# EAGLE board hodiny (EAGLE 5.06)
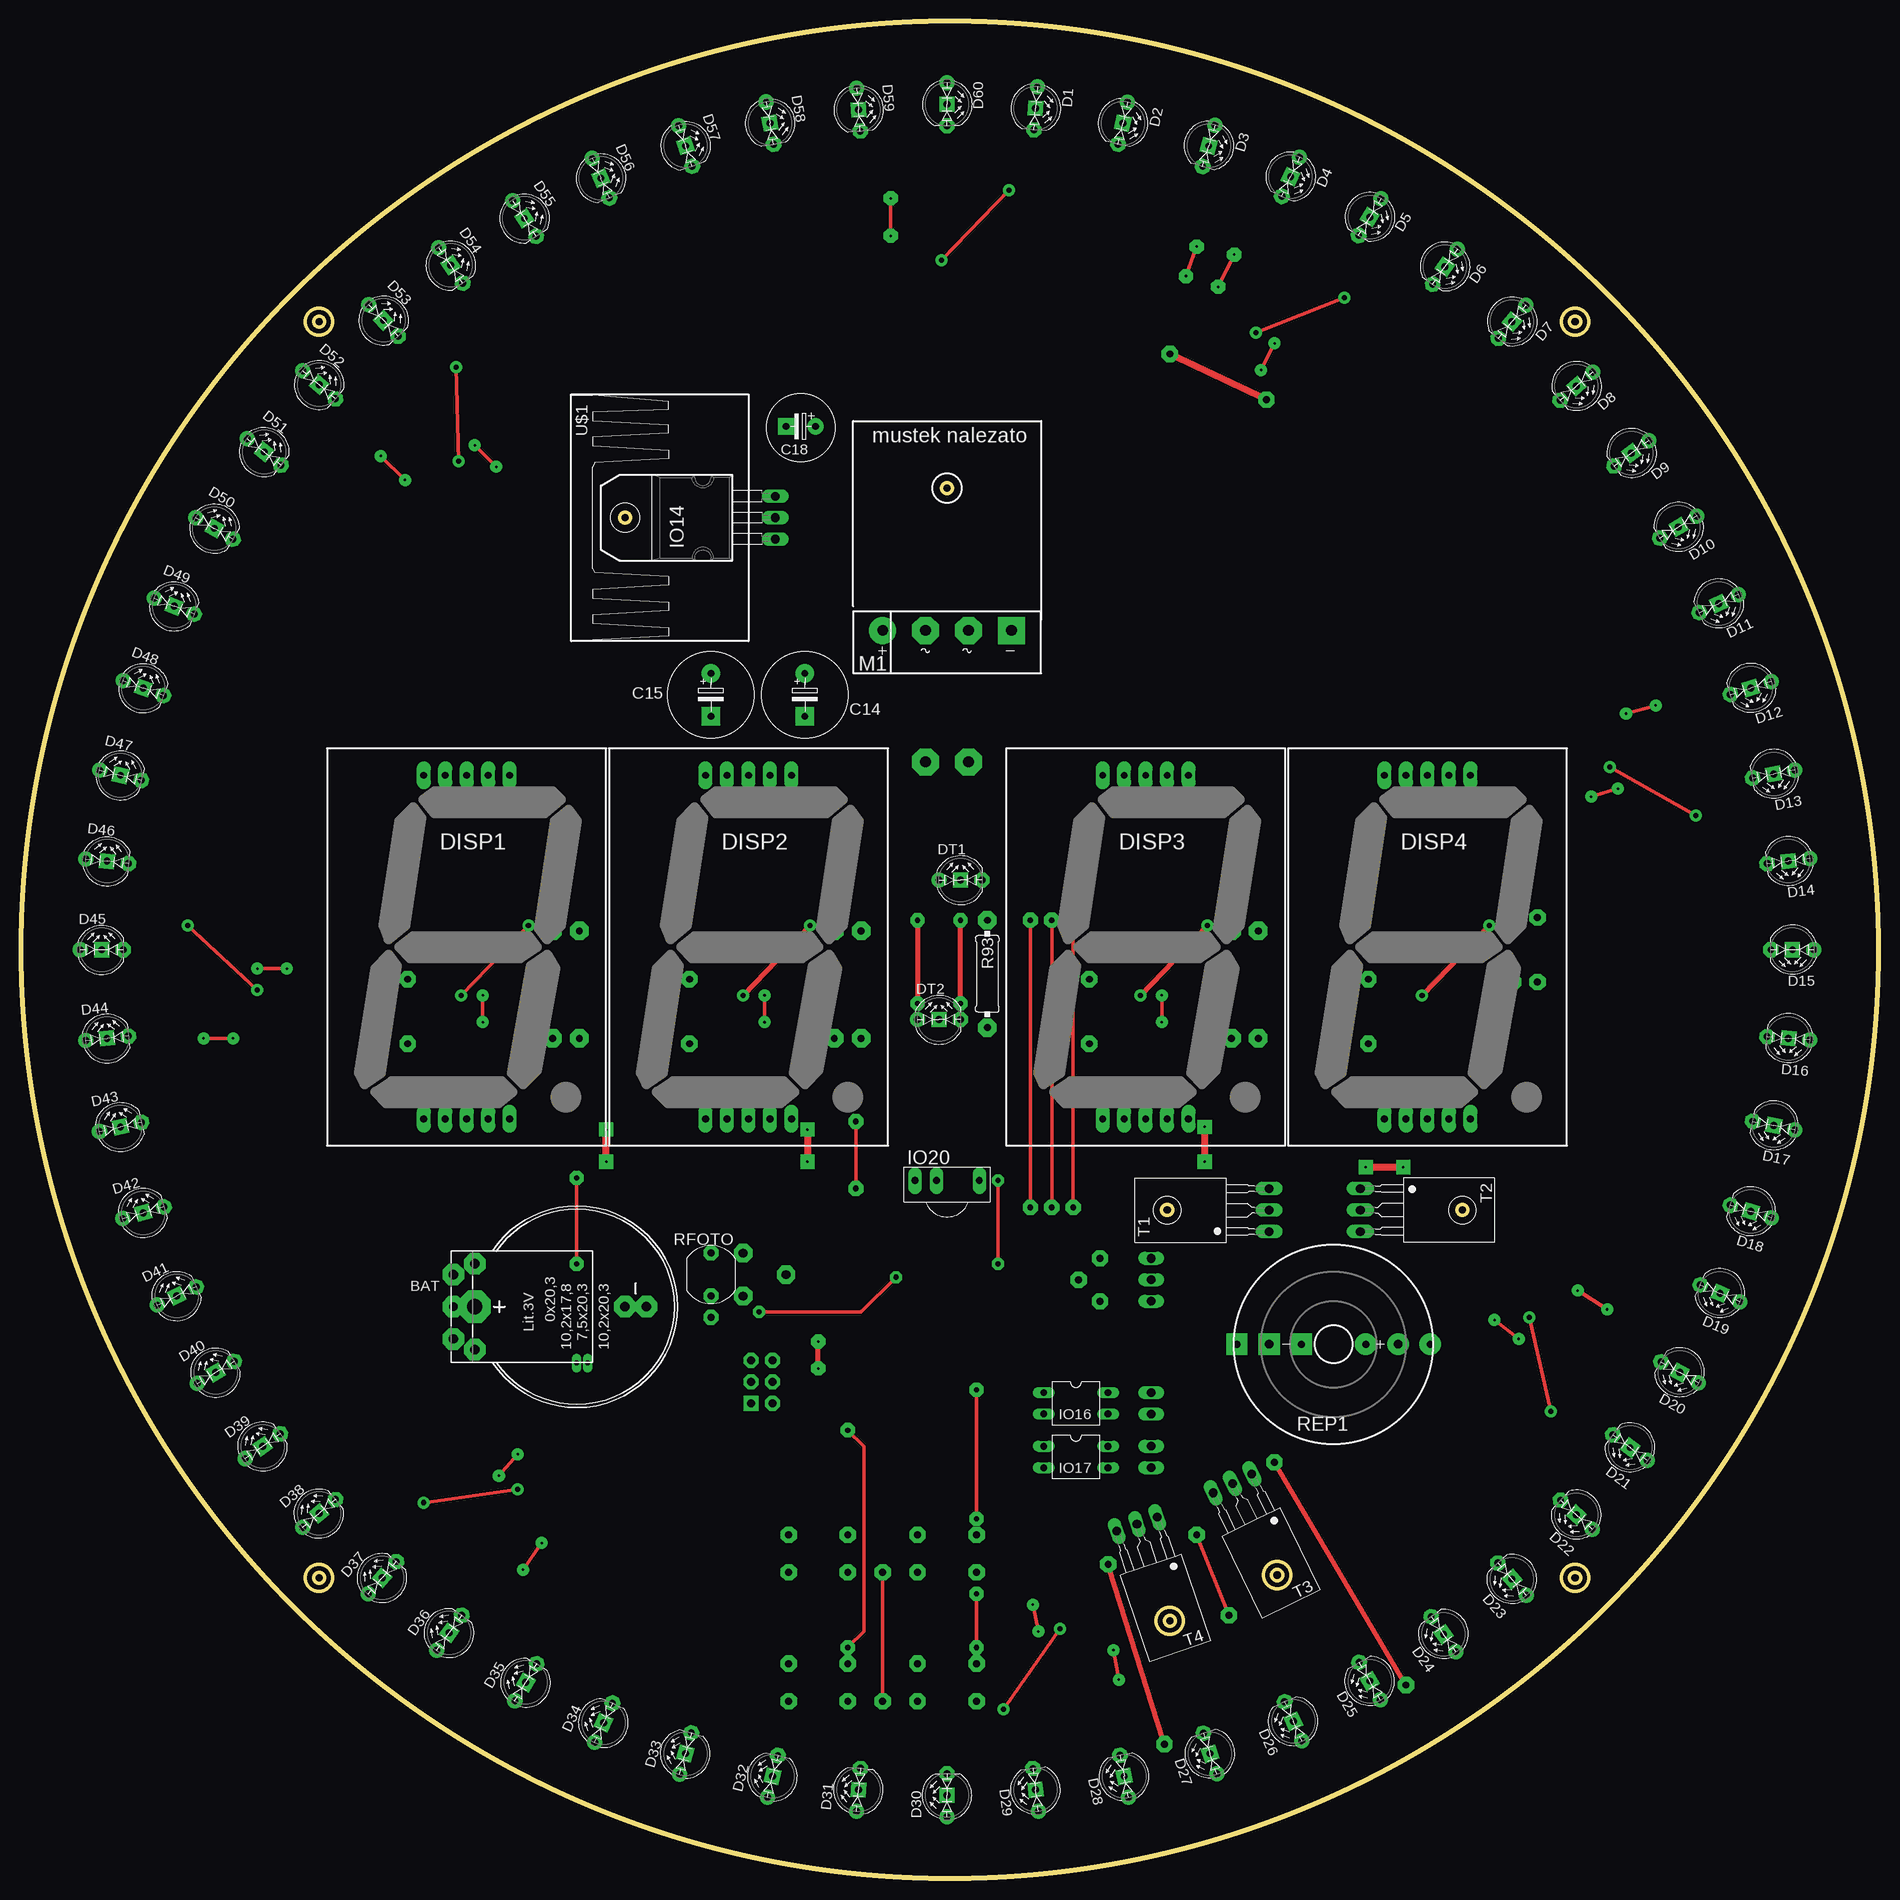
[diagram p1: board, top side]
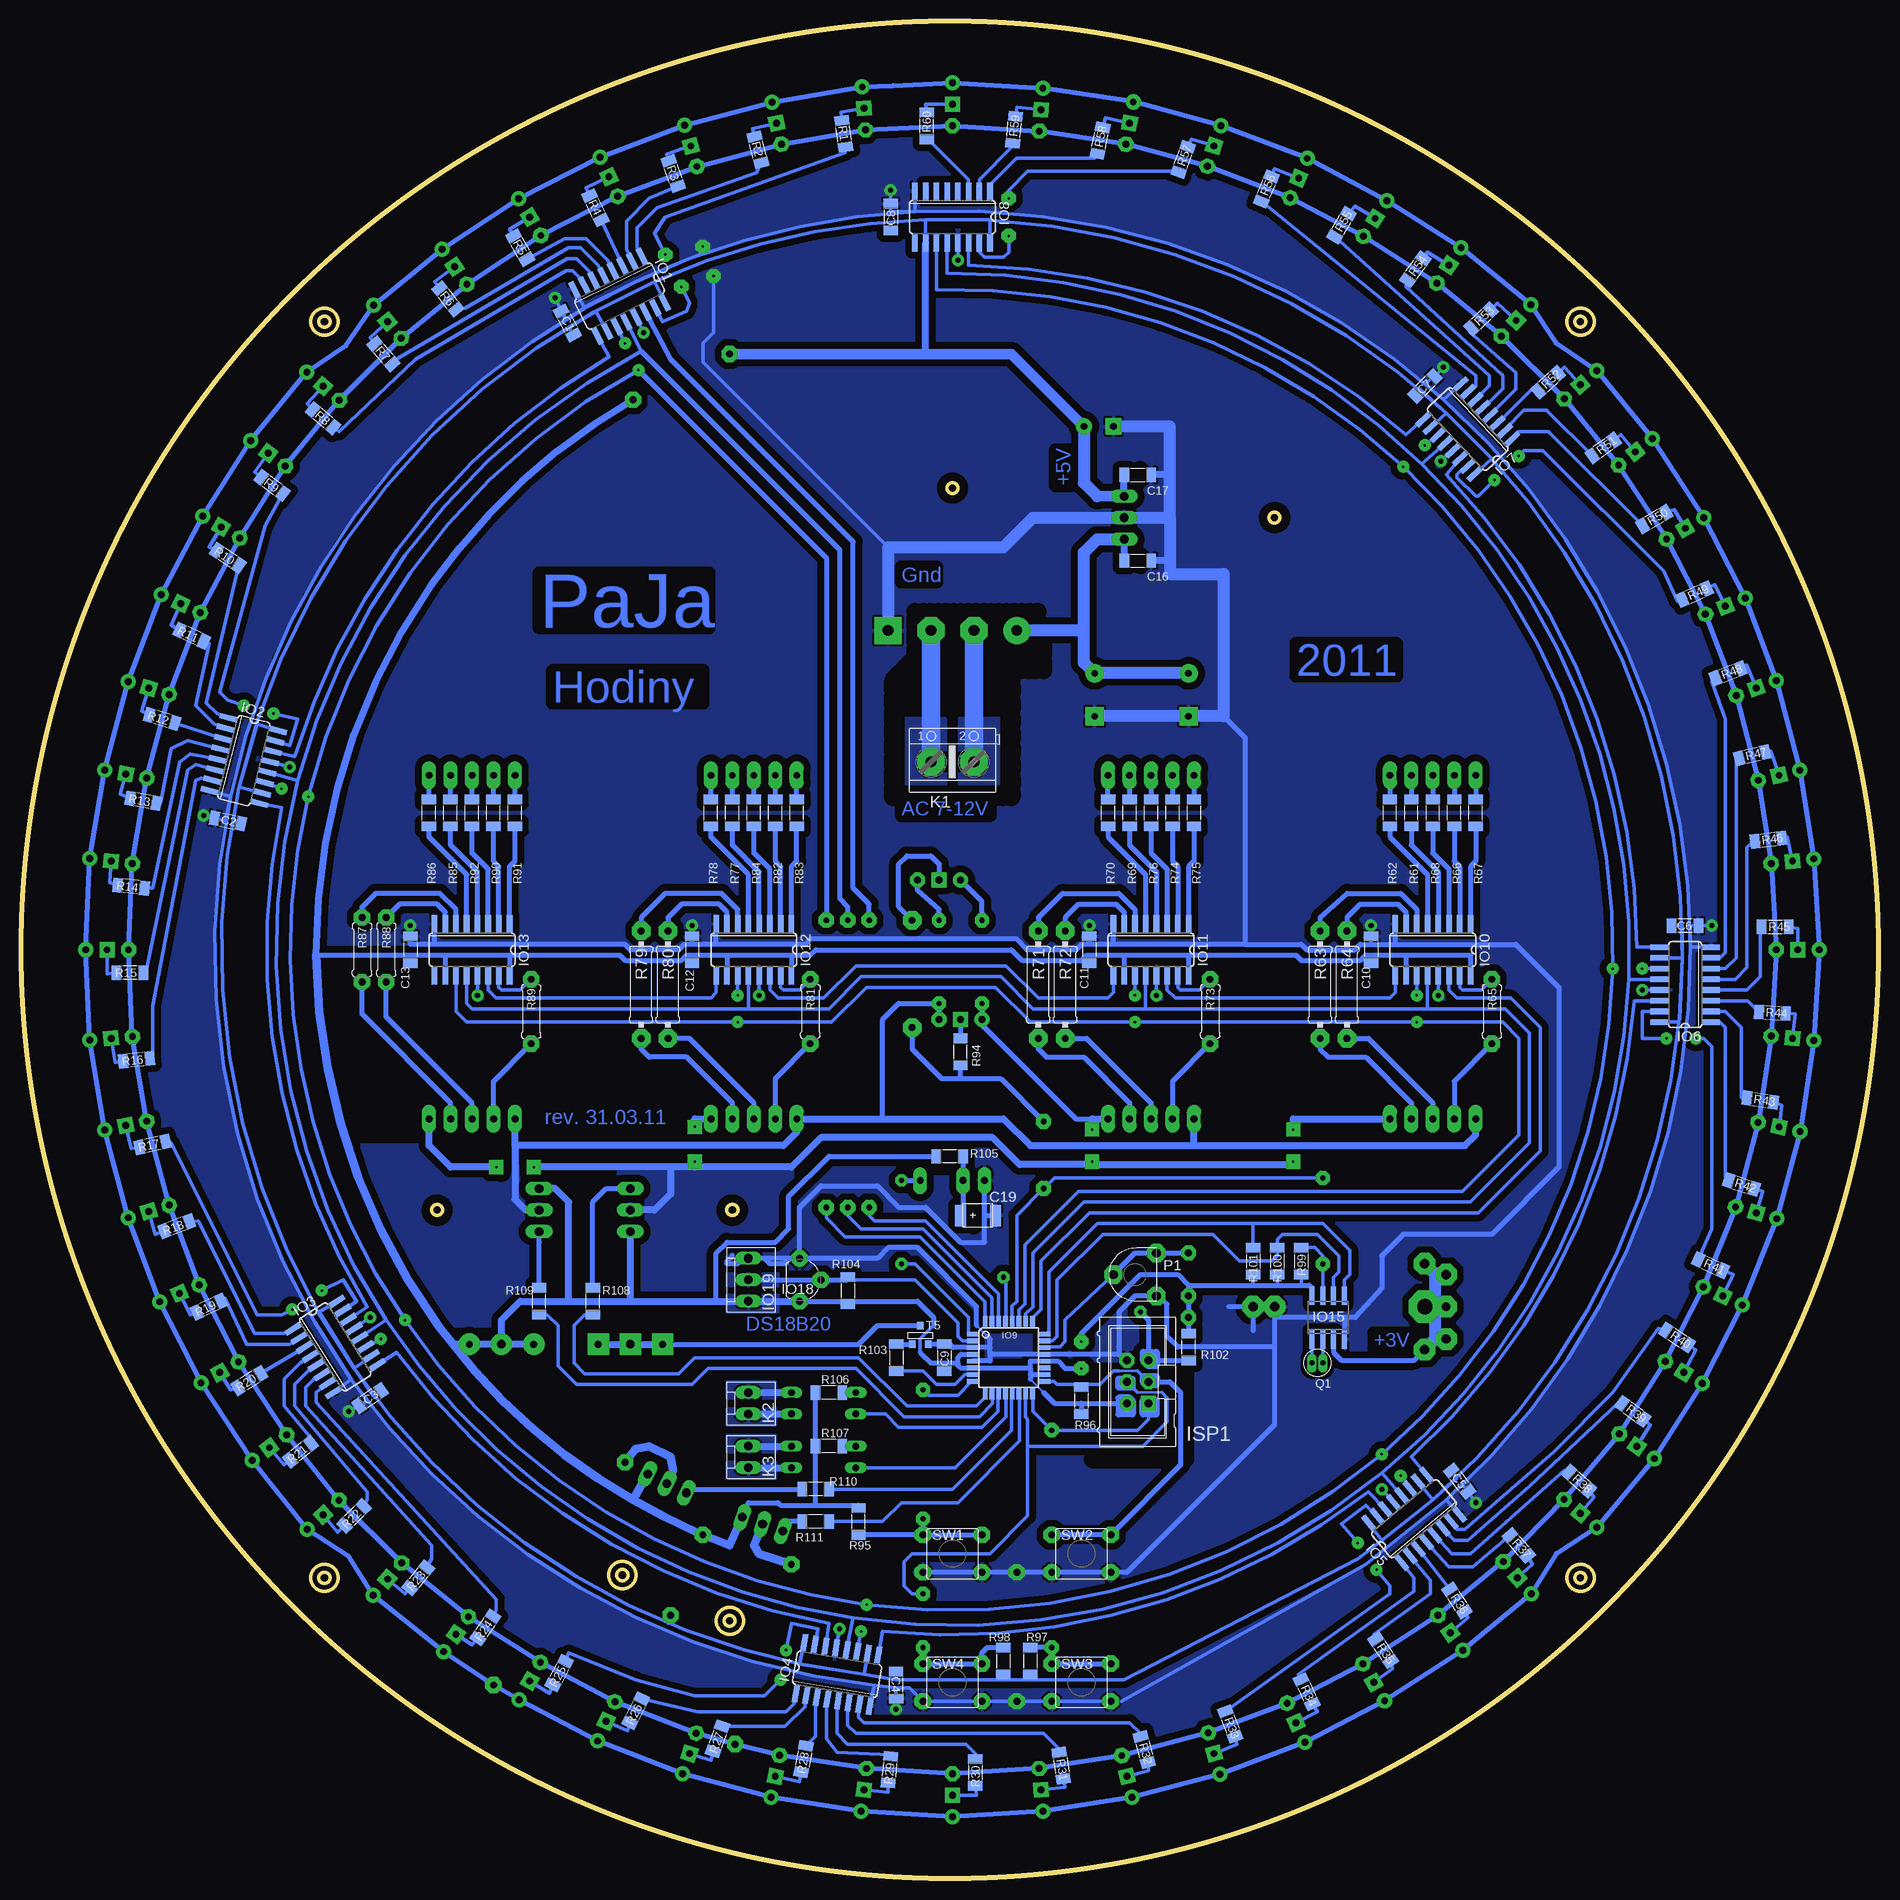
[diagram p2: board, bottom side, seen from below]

Size 219.71 x 219.71 mm. Coordinates in mm from the lower left corner, seen from the top.
Outline: circle at 109.86,109.86 radius 109.86
Outline: circle at 109.86,109.86 radius 109.86
Outline: circle at 109.86,109.86 radius 109.86
Outline: circle at 109.86,109.86 radius 109.86
Outline: circle at 109.54,164.47 radius 0.64
Outline: circle at 71.44,160.97 radius 0.64
Outline: circle at 35.24,184.15 radius 0.64
Outline: circle at 35.24,184.15 radius 1.59
Outline: circle at 183.83,184.15 radius 0.64
Outline: circle at 183.83,184.15 radius 1.59
Outline: circle at 183.83,35.56 radius 0.64
Outline: circle at 183.83,35.56 radius 1.59
Outline: circle at 35.24,35.56 radius 0.64
Outline: circle at 35.24,35.56 radius 1.59
Outline: circle at 148.59,35.88 radius 0.64
Outline: circle at 148.59,35.88 radius 1.59
Outline: circle at 135.89,30.48 radius 0.64
Outline: circle at 135.89,30.48 radius 1.59
Outline: circle at 135.57,79.06 radius 0.64
Outline: circle at 170.5,79.06 radius 0.64
Copper layers (1*16): Top 0.035mm / dielectric 1.5mm / Bottom 0.035mm
Design rules "default": minimum track width 10mil, minimum drill 24mil, track to track 8mil, track to pad 8mil, pad to pad 8mil, via to via 8mil, smd to smd 8mil, copper to edge 40mil, drill to drill 8mil, minimum pad ring 10mil, minimum via ring 8mil, stop-mask expansion 4mil, vias tented up to drill 0mil, thermal gap 10mil
bRestrict: area 81.9,62.2 to 86,67.3; 58 lines

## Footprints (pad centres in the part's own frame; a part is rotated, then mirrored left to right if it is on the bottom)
B2430UNI = drill 1.118 pad 2.54 octagon: + 3.81,14.605; +@1 -3.81,14.605; +@2 -5.08,12.065; +@3 5.08,12.065; - 0,-5.715; -@1 0,-8.255 | drill 1.803 pad 3.81 octagon: +@4 0,12.065
1206 = smd 1.143 x 1.702: 1 -1.587,0; 2 1.587,0
C_EL_5 = drill 0.813 pad 2.184 round: C+ -2.54,0 | drill 0.813 pad 2.184 square: C- 2.54,0
C_EL_3,5 = drill 0.813 pad 1.93 round: C+ 0,0 | drill 0.813 pad 1.93 square: C- 3.493,0
B = smd 1.27 x 2.54: + 2.223,0; - -1.905,0
LED_5-DUO = drill 0.813 pad 1.778 octagon: A1 2.54,0 | drill 0.813 pad 1.778 round: A2 -2.54,0 | drill 0.813 pad 1.778 square: K 0,0
HD-AB = drill 0.813 pad 1.676 long: 1 0,0; 2 2.54,0; 3 5.08,0; 4 7.62,0; 5 10.16,0; 6 10.16,40.64; 7 7.62,40.64; 8 5.08,40.64; 9 2.54,40.64; 10 0,40.64
SO16 = smd 0.66 x 2.032: 1 -4.445,-3.073; 2 -3.175,-3.073; 3 -1.905,-3.073; 4 -0.635,-3.073; 5 0.635,-3.073; 6 1.905,-3.073; 7 3.175,-3.073; 8 4.445,-3.073; 9 4.445,3.073; 10 3.175,3.073; 11 1.905,3.073; 12 0.635,3.073; 13 -0.635,3.073; 14 -1.905,3.073; 15 -3.175,3.073; 16 -4.445,3.073
TQFP32-08 = smd 1.27 x 0.559: 1 -4.293,2.8; 2 -4.293,2; 3 -4.293,1.2; 4 -4.293,0.4; 5 -4.293,-0.4; 6 -4.293,-1.2; 7 -4.293,-2; 8 -4.293,-2.8; 17 4.293,-2.8; 18 4.293,-2; 19 4.293,-1.2; 20 4.293,-0.4; 21 4.293,0.4; 22 4.293,1.2; 23 4.293,2; 24 4.293,2.8 | smd 0.559 x 1.27: 9 -2.8,-4.293; 10 -2,-4.293; 11 -1.2,-4.293; 12 -0.4,-4.293; 13 0.4,-4.293; 14 1.2,-4.293; 15 2,-4.293; 16 2.8,-4.293; 25 2.8,4.293; 26 2,4.293; 27 1.2,4.293; 28 0.4,4.293; 29 -0.4,4.293; 30 -1.2,4.293; 31 -2,4.293; 32 -2.8,4.293
TO-220 = drill 1.016 pad 1.6 long: 1 -2.54,0; 2 0,0; 3 2.54,0
SO08 = smd 0.6 x 2.2: 1 -1.905,-2.6; 2 -0.635,-2.6; 3 0.635,-2.6; 4 1.905,-2.6; 5 1.905,2.6; 6 0.635,2.6; 7 -0.635,2.6; 8 -1.905,2.6
DIL4 = drill 0.813 pad 1.27 long: 1 -1.27,-3.81; 2 1.27,-3.81; 3 1.27,3.81; 4 -1.27,3.81
TO-92 = drill 0.813 pad 1.93 octagon: 1 0,2.54; 2 2.54,0; 3 0,-2.54
PSH02-03P = drill 1.016 pad 1.422 long: 1 -2.54,0; 2 0,0; 3 2.54,0
SFH506 = drill 0.813 pad 1.6 long: 1 -3.81,0; 2 -1.27,0; 3 3.81,0
MLW06G = drill 0.914 pad 1.778 square: 1 -2.54,-1.27 | drill 0.914 pad 1.778 octagon: 2 -2.54,1.27; 3 0,-1.27; 4 0,1.27; 5 2.54,-1.27; 6 2.54,1.27
ARK500/2 = drill 1.27 pad 3.2 octagon: 1 -2.54,0; 2 2.54,0
PSH02-02P = drill 1.016 pad 1.422 long: 1 -1.27,0; 2 1.27,0
DM_KBU = drill 1.27 pad 3.2 round: + -7.62,2.857 | drill 1.27 pad 3.2 square: - 7.62,2.857 | drill 1.27 pad 3.2 octagon: AC1 -2.54,2.857; AC2 2.54,2.857
PT6V = drill 1.016 pad 2.184 octagon: 1 -2.54,-2.54; 2 0,2.54; 3 2.54,-2.54
Q_3X8 = drill 0.6 pad 0.813 long: 1 -0.635,0; 2 0.635,0
R-12,7 = drill 0.813 pad 2.184 octagon: 1 -6.35,0; 2 6.35,0
R-7,5 = drill 0.813 pad 1.93 octagon: 1 -3.81,0; 2 3.81,0
KPE212A = drill 1 pad 2.54 round: + -7.62,0 | drill 1 pad 2.54 square: - 7.62,0
R-FOTO = drill 0.813 pad 1.778 octagon: 1 -2.54,0; 2 2.54,0
P-B1720 = drill 0.813 pad 1.93 octagon: 1 -3.493,-2.223; 2 -3.493,2.223; 3 3.493,-2.223; 4 3.493,2.223
TO-126 = drill 1.016 pad 1.6 long: 1 -2.54,-12.065; 2 0,-12.065; 3 2.54,-12.065
SOT-23 = smd 0.787 x 0.889: 1 -0.953,-0.953; 2 0.953,-0.953; 3 0,1.27

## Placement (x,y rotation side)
BAT  CR2032  [B2430UNI]  65.72,67.63 90 top
C1  100n  [1206]  155.1,183.99 297.6 bottom
C2  100n  [1206]  195.26,125.09 348.6 bottom
C3  100n  [1206]  178.44,56.83 34.7 bottom
C4  100n  [1206]  116.21,22.86 90.1 bottom
C5  100n  [1206]  49.53,46.99 128 bottom
C6  100n  [1206]  22.86,112.71 180 bottom
C7  100n  [1206]  53.66,176.53 224.9 bottom
C8  100n  [1206]  116.84,196.53 270 bottom
C9  100n  [1206]  110.49,61.6 270 bottom
C10  100n  [1206]  60.01,109.86 270 bottom
C11  100n  [1206]  93.35,109.86 270 bottom
C12  100n  [1206]  140.34,109.86 270 bottom
C13  100n  [1206]  173.67,109.86 270 bottom
C14  470M/25V  [C_EL_5]  92.71,140.02 270 top
C15  470M/25V  [C_EL_5]  81.6,140.02 270 top
C16  100n  [1206]  87.63,155.89 0 bottom
C17  100n  [1206]  87.63,166.05 0 bottom
C18  220M/25V  [C_EL_3,5]  93.98,171.77 180 top
C19  4M7/10V  [B]  106.36,78.42 180 bottom
D1  RG  [LED_5-DUO]  120.02,209.39 265.6 top
D2  RG  [LED_5-DUO]  130.33,207.65 257.3 top
D3  RG  [LED_5-DUO]  140.49,204.95 253.5 top
D4  RG  [LED_5-DUO]  150.18,201.3 245.7 top
D5  RG  [LED_5-DUO]  159.54,196.53 238.7 top
D6  RG  [LED_5-DUO]  168.43,190.66 235 top
D7  RG  [LED_5-DUO]  176.37,184.15 230.3 top
D8  RG  [LED_5-DUO]  183.99,176.53 221.1 top
D9  RG  [LED_5-DUO]  190.5,168.59 216.3 top
D10  RG  [LED_5-DUO]  196.06,159.86 210.6 top
D11  RG  [LED_5-DUO]  200.82,150.81 204.8 top
D12  RG  [LED_5-DUO]  204.63,140.81 197.4 top
D13  RG  [LED_5-DUO]  207.33,130.65 190.8 top
D14  RG  [LED_5-DUO]  209.07,120.33 186.7 top
D15  RG  [LED_5-DUO]  209.55,109.86 180 top
D16  RG  [LED_5-DUO]  209.07,99.38 175.3 top
D17  RG  [LED_5-DUO]  207.33,89.06 168.4 top
D18  RG  [LED_5-DUO]  204.63,78.9 162.9 top
D19  RG  [LED_5-DUO]  200.98,69.22 156.9 top
D20  RG  [LED_5-DUO]  196.22,59.85 150.9 top
D21  RG  [LED_5-DUO]  190.34,50.96 143.3 top
D22  RG  [LED_5-DUO]  183.99,43.02 137.5 top
D23  RG  [LED_5-DUO]  176.37,35.4 131.4 top
D24  RG  [LED_5-DUO]  168.28,28.89 125.5 top
D25  RG  [LED_5-DUO]  159.54,23.34 119.8 top
D26  RG  [LED_5-DUO]  150.5,18.57 113.9 top
D27  RG  [LED_5-DUO]  140.65,14.76 108.3 top
D28  RG  [LED_5-DUO]  130.49,12.06 101.9 top
D29  RG  [LED_5-DUO]  120.02,10.48 97.2 top
D30  RG  [LED_5-DUO]  109.54,9.84 90 top
D31  RG  [LED_5-DUO]  99.06,10.48 84.9 top
D32  RG  [LED_5-DUO]  88.9,12.06 76 top
D33  RG  [LED_5-DUO]  78.58,14.76 73.8 top
D34  RG  [LED_5-DUO]  68.9,18.42 65.6 top
D35  RG  [LED_5-DUO]  59.69,23.18 59.7 top
D36  RG  [LED_5-DUO]  50.64,29.05 54.5 top
D37  RG  [LED_5-DUO]  42.7,35.56 49 top
D38  RG  [LED_5-DUO]  35.24,43.18 40.3 top
D39  RG  [LED_5-DUO]  28.58,51.12 35.1 top
D40  RG  [LED_5-DUO]  23.02,59.85 31 top
D41  RG  [LED_5-DUO]  18.42,68.9 25.2 top
D42  RG  [LED_5-DUO]  14.45,78.74 15.9 top
D43  RG  [LED_5-DUO]  11.75,88.9 12.4 top
D44  RG  [LED_5-DUO]  10.16,99.38 5.9 top
D45  RG  [LED_5-DUO]  9.53,109.86 0 top
D46  RG  [LED_5-DUO]  10.16,120.33 353.7 top
D47  RG  [LED_5-DUO]  11.75,130.49 346.4 top
D48  RG  [LED_5-DUO]  14.45,140.81 339.6 top
D49  RG  [LED_5-DUO]  18.1,150.5 338.2 top
D50  RG  [LED_5-DUO]  22.86,159.7 329.6 top
D51  RG  [LED_5-DUO]  28.73,168.75 322.1 top
D52  RG  [LED_5-DUO]  35.24,176.69 319.4 top
D53  RG  [LED_5-DUO]  42.86,184.31 313.1 top
D54  RG  [LED_5-DUO]  50.8,190.82 304.4 top
D55  RG  [LED_5-DUO]  59.53,196.37 303.7 top
D56  RG  [LED_5-DUO]  68.58,201.14 293.4 top
D57  RG  [LED_5-DUO]  78.58,204.95 288.5 top
D58  RG  [LED_5-DUO]  88.58,207.65 279.8 top
D59  RG  [LED_5-DUO]  99.06,209.23 274.7 top
D60  RG  [LED_5-DUO]  109.54,209.87 270 top
DISP1  SBA15-11EGWA  [HD-AB]  47.63,89.85 0 top
DISP2  SBA15-11EGWA  [HD-AB]  80.96,89.85 0 top
DISP3  SBA15-11EGWA  [HD-AB]  127.95,89.85 0 top
DISP4  SBA15-11EGWA  [HD-AB]  161.29,89.85 0 top
DT1  RG  [LED_5-DUO]  111.13,118.11 0 top
DT2  RG  [LED_5-DUO]  108.59,101.6 0 top
IO1  74HC595D  [SO16]  148.91,187.17 206.5 bottom
IO2  74HC595D  [SO16]  193.36,132.24 255.6 bottom
IO3  74HC595D  [SO16]  182.56,62.87 302.3 bottom
IO4  74HC595D  [SO16]  123.19,24.13 350.4 bottom
IO5  74HC595D  [SO16]  54.93,42.55 39.8 bottom
IO6  74HC595D  [SO16]  22.86,105.73 90 bottom
IO7  74HC595D  [SO16]  48.58,171.45 133.4 bottom
IO8  74HC595D  [SO16]  109.54,196.53 180 bottom
IO9  ATMEGA168-AU  [TQFP32-08]  102.87,61.6 0 bottom
IO10  74HC595D  [SO16]  52.71,109.86 180 bottom
IO11  74HC595D  [SO16]  86.04,109.86 180 bottom
IO12  74HC595D  [SO16]  133.03,109.86 180 bottom
IO13  74HC595D  [SO16]  166.37,109.86 180 bottom
IO14  78S05  [TO-220]  89.22,160.97 90 top
IO15  DS1307  [SO08]  65.09,66.36 0 bottom
IO16  PC815  [DIL4]  124.78,56.2 270 top
IO17  PC815  [DIL4]  124.78,49.85 270 top
IO18  DS18B20  [TO-92]  127.64,70.8 0 bottom
IO19  DS18B20  [PSH02-03P]  133.67,70.8 90 bottom
IO20  SFH506  [SFH506]  109.54,82.55 0 top
ISP1  AVR_ISP  [MLW06G]  87.63,58.74 90 bottom
K1  AC 7-12V  [ARK500/2]  109.54,132.08 0 bottom
K2  [PSH02-02P]  133.67,56.2 90 bottom
K3  [PSH02-02P]  133.67,49.85 90 bottom
M1  B250C8000  [DM_KBU]  109.54,144.78 0 top
P1  5k  [PT6V]  87.95,71.44 90 bottom
Q1  32,768kHz  [Q_3X8]  66.36,60.96 180 bottom
R1  330  [1206]  122.4,206.39 97.6 bottom
R2  330  [1206]  132.56,204.52 104.2 bottom
R3  330  [1206]  142.56,201.7 109.1 bottom
R4  330  [1206]  151.76,197.64 115.6 bottom
R5  330  [1206]  160.66,192.93 119.6 bottom
R6  330  [1206]  169.23,186.85 128.3 bottom
R7  330  [1206]  176.85,180.34 130.7 bottom
R8  330  [1206]  183.99,172.72 139.7 bottom
R9  330  [1206]  190.02,164.78 142.7 bottom
R10  330  [1206]  195.26,156.21 145.9 bottom
R11  330  [1206]  199.55,147 155.2 bottom
R12  330  [1206]  203.04,137.16 162.9 bottom
R13  330  [1206]  205.26,127.48 169.6 bottom
R14  330  [1206]  206.69,117.32 173.6 bottom
R15  330  [1206]  206.85,107.16 180 bottom
R16  330  [1206]  206.06,96.84 186.1 bottom
R17  330  [1206]  204.15,86.84 192.5 bottom
R18  330  [1206]  201.3,77.15 200.1 bottom
R19  330  [1206]  197.49,67.63 205.5 bottom
R20  330  [1206]  192.72,58.9 211.9 bottom
R21  330  [1206]  186.69,50.48 218.9 bottom
R22  330  [1206]  180.34,42.86 225 bottom
R23  330  [1206]  172.72,35.56 230.7 bottom
R24  330  [1206]  164.78,29.69 235.5 bottom
R25  330  [1206]  156.05,24.29 241.6 bottom
R26  330  [1206]  147,19.84 243.5 bottom
R27  330  [1206]  137.32,16.51 250.7 bottom
R28  330  [1206]  127.16,14.13 259.6 bottom
R29  330  [1206]  117,12.86 264.8 bottom
R30  330  [1206]  106.84,12.54 270 bottom
R31  330  [1206]  96.68,13.34 278.8 bottom
R32  330  [1206]  86.84,15.24 285.5 bottom
R33  330  [1206]  76.68,18.26 290.5 bottom
R34  330  [1206]  67.63,22.07 294.7 bottom
R35  330  [1206]  58.58,26.99 303.7 bottom
R36  330  [1206]  49.85,32.86 302.9 bottom
R37  330  [1206]  42.55,39.37 311 bottom
R38  330  [1206]  35.4,46.99 318.1 bottom
R39  330  [1206]  29.05,55.25 323.1 bottom
R40  330  [1206]  23.81,63.98 326.5 bottom
R41  330  [1206]  19.84,72.55 335.6 bottom
R42  330  [1206]  16.19,82.07 341.7 bottom
R43  330  [1206]  13.97,92.08 351.2 bottom
R44  330  [1206]  12.54,102.39 356.7 bottom
R45  330  [1206]  12.22,112.55 0 bottom
R46  330  [1206]  13.02,122.87 6.9 bottom
R47  330  [1206]  14.92,132.87 13.2 bottom
R48  330  [1206]  17.78,142.56 20.7 bottom
R49  330  [1206]  21.75,151.92 24 bottom
R50  330  [1206]  26.51,160.81 30.1 bottom
R51  330  [1206]  32.54,169.23 35.9 bottom
R52  330  [1206]  39.05,177.01 42.4 bottom
R53  330  [1206]  46.99,184.47 43.2 bottom
R54  330  [1206]  54.77,190.34 54.1 bottom
R55  330  [1206]  63.5,195.58 59.5 bottom
R56  330  [1206]  72.39,199.87 67.5 bottom
R57  330  [1206]  82.23,203.36 70.3 bottom
R58  330  [1206]  92.08,205.58 78.5 bottom
R59  330  [1206]  102.24,206.85 84 bottom
R60  330  [1206]  112.55,207.33 90 bottom
R61  180  [1206]  55.25,126.05 90 bottom
R62  180  [1206]  57.79,126.05 90 bottom
R63  180  [R-12,7]  66.04,105.73 270 bottom
R64  180  [R-12,7]  62.87,105.73 270 bottom
R65  180  [R-7,5]  45.72,102.55 270 bottom
R66  180  [1206]  50.17,126.05 90 bottom
R67  180  [1206]  47.63,126.05 90 bottom
R68  470  [1206]  52.71,126.05 90 bottom
R69  180  [1206]  88.58,126.05 90 bottom
R70  180  [1206]  91.12,126.05 90 bottom
R71  180  [R-12,7]  99.38,105.73 270 bottom
R72  180  [R-12,7]  96.2,105.73 270 bottom
R73  180  [R-7,5]  79.06,102.55 270 bottom
R74  180  [1206]  83.5,126.05 90 bottom
R75  180  [1206]  80.96,126.05 90 bottom
R76  470  [1206]  86.04,126.05 90 bottom
R77  180  [1206]  135.57,126.05 90 bottom
R78  180  [1206]  138.11,126.05 90 bottom
R79  180  [R-12,7]  146.37,105.73 270 bottom
R80  180  [R-12,7]  143.19,105.73 270 bottom
R81  180  [R-7,5]  126.37,102.55 270 bottom
R82  180  [1206]  130.49,126.05 90 bottom
R83  180  [1206]  127.95,126.05 90 bottom
R84  470  [1206]  133.03,126.05 90 bottom
R85  180  [1206]  168.91,126.05 90 bottom
R86  180  [1206]  171.45,126.05 90 bottom
R87  180  [R-7,5]  179.39,109.86 270 bottom
R88  180  [R-7,5]  176.53,109.86 270 bottom
R89  180  [R-7,5]  159.38,102.55 270 bottom
R90  180  [1206]  163.83,126.05 90 bottom
R91  180  [1206]  161.29,126.05 90 bottom
R92  470  [1206]  166.37,126.05 90 bottom
R93  470  [R-12,7]  114.3,107 90 top
R94  470  [1206]  108.59,97.79 90 bottom
R95  10k  [1206]  120.65,42.23 90 bottom
R96  10k  [1206]  94.3,56.52 270 bottom
R97  10k  [1206]  100.33,25.72 270 bottom
R98  10k  [1206]  103.51,25.72 270 bottom
R99  10k  [1206]  68.26,73.03 270 bottom
R100  10k  [1206]  71.12,73.03 270 bottom
R101  10k  [1206]  73.98,73.03 270 bottom
R102  4k7  [1206]  81.6,62.87 90 bottom
R103  4k7  [1206]  116.21,61.6 270 bottom
R104  4k7  [1206]  121.92,69.53 270 bottom
R105  220  [1206]  109.86,85.41 180 bottom
R106  330  [1206]  124.14,57.47 180 bottom
R107  330  [1206]  124.14,51.12 180 bottom
R108  1k  [1206]  152.08,68.26 90 bottom
R109  1k  [1206]  158.43,68.26 90 bottom
R110  1k  [1206]  125.73,46.04 180 bottom
R111  1k  [1206]  125.73,42.23 180 bottom
REP1  KPE212A  [KPE212A]  155.26,63.18 180 top
RFOTO  VT43N1  [R-FOTO]  81.6,71.44 270 top
SW1  P-B1720  [P-B1720]  109.54,38.42 0 bottom
SW2  P-B1720  [P-B1720]  94.3,38.42 0 bottom
SW3  P-B1720  [P-B1720]  94.3,23.18 0 bottom
SW4  P-B1720  [P-B1720]  109.54,23.18 0 bottom
T1  BD140  [TO-126]  135.57,79.06 90 top
T2  BD140  [TO-126]  170.5,79.06 270 top
T3  BD140  [TO-126]  148.59,35.88 206 top
T4  BD140  [TO-126]  135.89,30.48 198.8 top
T5  BC817  [SOT-23]  113.35,64.14 0 bottom
U$1  [CH_V4330N]  67.63,160.97 270 top

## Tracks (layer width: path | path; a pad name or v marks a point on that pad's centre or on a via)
+5V  (via drill 0.3 pad 1.68, 0.8 pad 2.54, 0.81 pad 1.78, 0.81 pad 1.93, 0.81 pad 2.54)
  Top 0.406: v139.06,40.64 v142.87,31.12
  Top 0.61: v94.3,60.33 v94.3,63.5
  Top 0.813: v147.32,174.94 v135.89,180.34
  Bottom 0.305: 100.33,59.06 98.74,57.47
  Bottom 0.406: 144.78,188.91 arc-53 193.99,128.91 | IO2.16 191.77,136.53 193.94,129.08 | 193.99,128.91 193.94,129.08 | 193.94,129.08 IO2.10 | 144.78,188.91 IO1.16 | 151.71,185.32 151.76,185.42 144.78,188.91 | 151.71,185.32 IO1.10 | C1.2 154.94,183.51 151.71,185.32 | 193.99,128.91 arc-47 180.34,60.33 | 180.34,60.33 arc-49 120.01,24.13 | IO4.16 127.64,25.4 120.01,24.13 | 180.34,60.33 IO3.10 | IO3.16 184.47,66.99 180.34,60.33 | C3.2 178.12,57.15 180.34,60.33 | 23.18,108.9 arc48 52.7,44.77 | 51.12,173.36 arc48 23.18,108.9 | 112.71,196.22 arc45 51.12,173.36 | IO8.16 105.09,196.22 112.71,196.22 | IO8.10 112.71,196.22 | 51.12,173.36 IO7.10 | 51.12,173.36 54.29,176.21 C7.2 | IO7.16 45.72,167.96 51.12,173.36 | IO6.16 23.81,101.28 23.49,101.6 23.18,108.9 | 23.18,108.9 IO6.10 | C6.2 23.18,112.71 23.18,108.9 | 52.7,44.77 IO5.10 | 52.7,44.77 49.85,47.31 C5.2 | 58.74,40.01 IO5.16 | 52.7,44.77 58.74,40.01 | 120.01,24.13 IO4.10 | 120.01,24.13 116.21,23.5 | C2.2 194.63,125.09 193.99,128.91 | 60.01,109.22 C10.2 | 93.03,109.22 93.35,109.22 | 162.24,109.22 161.93,109.22 161.61,109.22 | 169.23,109.22 169.55,109.22 | 136.53,109.22 136.21,109.22 | 110.42,60.4 110.49,60.33 C9.2 | 113.35,62.23 113.35,63.82 111.76,65.41 | 116.21,23.5 103.51,23.5 | 103.51,23.5 100.33,23.5 | 100.33,23.5 89.22,23.5 61.59,37.78 58.74,40.01 | C4.2 116.21,23.5 | 112.71,196.22 arc-22 144.78,188.91 | C8.2 116.84,195.9 112.71,196.22 | 121.92,68.26 R104.2 | 100.33,23.5 R97.2 | 103.51,23.5 R98.2 | ISP1.2 89.53,55.56 | 120.65,44.13 R95.2 | v142.87,31.12 143.19,30.16 | 135.89,39.37 v139.06,40.64 | 73.98,70.17 R101.2 | 71.12,70.17 R100.2 | 68.26,70.17 R99.2
  Bottom 0.61: IO10.16 48.26,109.22 55.88,109.22 | 55.88,109.22 60.01,109.22 60.64,109.22 61.28,108.59 68.26,108.59 68.9,109.22 81.6,109.22 | 55.88,109.22 IO10.10 | 140.33,109.22 136.53,109.22 128.59,109.22 | 89.22,109.22 93.03,109.22 93.66,109.22 94.3,108.59 101.28,108.59 102.55,109.86 125.73,109.86 126.37,109.22 128.59,109.22 | 89.22,109.22 81.6,109.22 | 173.67,109.22 169.23,109.22 162.24,109.22 148.91,109.22 148.27,108.59 141.61,108.59 140.97,109.22 140.33,109.22 | 173.67,109.22 C13.2 | 161.93,109.22 IO13.16 | 169.55,109.22 IO13.10 | 140.33,109.22 C12.2 | 136.21,109.22 IO12.10 | 128.59,109.22 IO12.16 | 81.6,109.22 IO11.16 | 89.22,109.22 IO11.10 | 93.35,109.22 C11.2 | 184.79,109.22 173.67,109.22 | 111.76,65.41 111.76,66.36 113.67,68.26 121.92,68.26 IO18.3 | R106.2 R107.2 125.73,44.13 | 125.73,44.13 129.86,44.13 130.17,44.45 133.67,44.45 T4.1 | 81.6,70.17 82.87,71.44 87.31,71.44 94.3,64.45 v94.3,63.5 | 81.6,70.17 RFOTO.2 v81.6,66.36 R102.2 | v94.3,60.33 96.2,60.33 97.07,61.2 IO9.20 100.33,61.2 100.33,60.33 | 125.73,44.13 120.65,44.13 | 137.48,68.26 137.48,73.98 136.21,75.25 130.49,75.25 128.9,76.84 128.9,80.65 124.14,85.41 R105.2 | 81.6,70.17 73.98,70.17 71.12,70.17 68.26,70.17 67.31,70.17 66.99,69.85 IO15.8 | 100.33,59.6 IO9.18 | 100.33,60.33 100.33,59.6 | 100.33,59.6 100.33,59.06 | 98.74,57.47 97.47,56.2 94.3,56.2 | 94.3,56.2 ISP1.2 | 94.3,56.2 R96.2 | 108.9,60.96 108.9,61.6 108.5,62 IO9.4 | 108.9,60.96 108.9,60.64 108.58,60.4 IO9.6 100.4,60.4 arc90 100.33,60.33 | 113.35,62.23 112.08,60.96 110.49,60.96 | 110.49,60.96 108.9,60.96 | 110.42,60.4 110.49,60.47 110.49,60.96
  Bottom 0.813: T2.1 156.53,81.6 154.94,80.01 154.94,68.26 | v159.07,63.18 REP1.+ | 147.64,68.26 T1.1 | 154.94,68.26 147.64,68.26 | 154.94,68.26 160.65,68.26 162.88,66.04 REP1.+ | 184.79,109.22 arc35 171.13,153.03 arc25 v147.32,174.94 | IO14.3 C17.1 | 112.71,180.34 IO8.10 | 147.64,68.26 137.48,68.26 IO19.1 IO18.3 | 88.26,56.52 88.26,54.93 89.85,54.93 89.85,56.83 88.58,56.83 88.26,56.52 | 88.26,56.52 88.58,56.52 ISP1.2 | REP1.+ v166.69,63.18 168.59,63.18 166.05,60.01
  Bottom 1.016: 147.32,44.77 arc-9 135.89,39.37 T4.1 | 147.32,44.77 T3.1 | 184.79,109.22 arc-41 166.05,60.01 arc-19 147.32,44.77
  Bottom 1.27: 92.39,163.51 IO14.3 | v135.89,180.34 112.71,180.34 108.27,180.34 | 108.27,180.34 107.95,180.34 | C18.C+ 102.55,180.34 108.27,180.34
  Bottom 1.422: 92.39,163.51 93.98,165.1 C18.C+
  pour Bottom (isolate 0.254): 130.18,69.22 136.21,69.22 136.21,66.99 130.18,66.99
+BAT  (via drill 1 pad 2.54)
  Bottom 0.406: 52.39,67.63 v51.12,67.63
  Bottom 0.61: IO15.3 64.45,62.23 63.5,61.28 54.93,61.28 53.66,62.55
  Bottom 1.422: 52.39,71.44 BAT.+ | 52.39,71.44 53.66,72.71 | 53.66,62.55 52.39,63.82 | 52.39,71.44 52.39,67.63 52.39,63.82 | 52.39,63.82 51.12,63.82
+SFH
  Bottom 0.406: 108.27,78.42 C19.+
  Bottom 0.61: 108.27,78.42 IO20.2 R105.1
AC1
  Bottom 2.184: K1.2 M1.AC1
  pour Bottom (isolate 1.016): 103.51,127.95 108.59,127.95 108.59,137.16 103.51,137.16
AC2
  Bottom 2.184: K1.1 M1.AC2
  pour Bottom (isolate 1.016): 110.49,137.16 110.49,127.95 115.57,127.95 115.57,137.16
CLK  (via drill 0.3 pad 1.42)
  Top 0.406: v54.61,101.28 v54.61,104.46 | v87.95,101.28 v87.95,104.46 | v134.94,101.28 v134.94,104.46
  Bottom 0.406: v54.61,104.46 IO10.11 | v87.95,104.46 IO11.11 | v134.94,104.46 IO12.11 | IO13.11 168.27,102.55 167.01,101.28 v134.94,101.28 123.82,101.28 119.7,105.41 104.46,105.41 100.33,101.28 v87.95,101.28 v54.61,101.28 44.45,101.28 42.54,99.38 42.54,87.95 49.21,81.28 94.62,81.28 100.97,74.93 100.97,67.95 101.67,67.24 IO9.27
CLK_LED  (via drill 0.3 pad 1.42, 0.7 pad 1.78)
  Top 0.406: v119.7,32.39 v120.33,29.21 | v174.31,66.04 v177.16,63.82 | v58.74,50.17 v56.51,47.63 | v31.43,107.63 v27.94,107.63 | v53.66,169.55 v56.2,167 | v146.69,178.44 v148.27,181.61 | v185.74,127.95 v188.91,128.91 | v124.46,113.35 v124.46,79.38
  Bottom 0.406: v188.91,128.91 IO2.11 | v146.69,178.44 arc-48 v185.74,127.95 arc-48 v174.31,66.04 arc-48 v119.7,32.39 arc-47 v58.74,50.17 arc-48 v31.43,107.63 arc-48 v56.2,167 arc-44 111.44,187.96 IO8.11 | v120.33,29.21 IO4.11 | v56.51,47.63 IO5.11 | v27.94,107.63 IO6.11 | IO7.11 v53.66,169.55 | v148.27,181.61 IO1.11 | v177.16,63.82 IO3.11 | v124.46,79.38 124.46,78.11 122.24,75.88 113.35,75.88 105.67,68.21 IO9.32
  Bottom 0.61: v146.69,178.44 124.46,156.21 v124.46,113.35
DATA
  Bottom 0.406: IO10.14 50.8,105.09 49.85,104.14 43.5,104.14 40.01,100.65 40.01,86.04 47.31,78.74 93.35,78.74 99.06,73.03 99.06,67.31 100.07,66.3 IO9.25
DATA_IR  (via drill 0.6 pad 1.42)
  Top 0.406: v115.57,82.55 v115.57,72.71
  Bottom 0.406: IO9.1 107.22,64.45 107.63,64.45 107.63,66.36 113.98,72.71 v115.57,72.71
  Bottom 0.61: v115.57,82.55 IO20.3
DATA_LED  (via drill 0.7 pad 1.78)
  Top 0.406: v119.38,113.35 v119.38,79.38
  Bottom 0.406: IO9.30 104.07,69.15 112.71,77.79 118.74,77.79 119.38,78.42 v119.38,79.38
  Bottom 0.61: IO1.14 142.87,179.7 121.29,158.12 121.29,117.16 119.38,115.25 v119.38,113.35
DES.TECKA  (via drill 0.6 pad 1.68, 0.7 pad 1.78)
  Top 0.406: v98.74,89.53 v98.74,81.6 | v65.72,82.87 v65.72,72.71
  Bottom 0.406: IO9.28 102.47,67.71 101.92,68.26 101.92,78.42 v98.74,81.6 97.47,82.87 v65.72,82.87 | v65.72,72.71 65.72,72.39 | v65.72,72.71 IO15.7 | v65.72,72.71 65.72,73.66 66.68,74.61 R99.1
  Bottom 0.61: R93.1 114.3,98.11 110.81,94.62 108.58,94.62 | v98.74,89.53 103.82,94.62 108.58,94.62 | 108.58,94.62 R94.1
GND  (via drill 0.3 pad 1.68, 0.6 pad 1.42, 0.81 pad 1.93)
  Top 0.406: v156.53,187.01 v146.05,182.88 | v198.12,125.73 v187.96,131.44 | v180.98,55.25 v178.43,66.36 | v116.21,20 v122.87,29.53 | v47.62,44.45 v58.74,46.04 | v19.68,112.71 v27.94,105.09 | v51.75,167.64 v51.44,178.75 | v116.84,199.71 v108.9,191.45 | v60.01,112.71 v52.07,104.46 | v139.06,193.04 v137.8,189.55 | v101.92,36.2 v101.92,20.95
  Top 0.61: v173.67,112.71 v165.73,104.46 | v93.35,112.71 v85.41,104.46 | v140.33,112.71 v132.4,104.46
  Bottom 0.305: 105.41,64.14 106.68,65.41
  Bottom 0.406: 137.8,110.49 137.48,110.49 | v146.05,182.88 IO1.13 | 153.04,185.74 arc-48 194.94,127.95 | 194.94,127.95 IO2.8 | 194.94,127.95 195.58,125.09 C2.1 v198.12,125.73 | 153.04,185.74 153.09,185.84 | 153.09,185.84 IO1.8 | 153.04,185.74 155.26,184.47 C1.1 v156.53,187.01 | 194.94,127.95 arc-47 180.66,59.06 | 180.66,59.06 arc-48 118.74,22.86 | 22.23,110.17 arc48 51.12,44.77 | 51.44,174.94 arc48 22.23,110.17 | 51.44,174.94 arc-45 113.98,197.17 | 113.98,197.17 IO8.8 | 51.44,174.94 IO7.8 | 51.44,174.94 53.66,176.85 C7.1 v51.44,178.75 | 22.23,110.17 22.23,112.71 C6.1 v19.68,112.71 | 22.23,110.17 IO6.8 | 51.12,44.77 IO5.8 | 51.12,44.77 49.21,46.67 C5.1 v47.62,44.45 | 118.74,22.86 IO4.8 | 180.66,59.06 IO3.8 | 180.66,59.06 178.75,56.52 C3.1 v180.98,55.25 | v187.96,131.44 IO2.13 | v178.43,66.36 IO3.13 | v122.87,29.53 IO4.13 | v58.74,46.04 IO5.13 | v27.94,105.09 IO6.13 | IO7.13 v51.75,167.64 | v108.9,191.45 IO8.13 | C8.1 v116.84,199.71 116.84,197.17 113.98,197.17 | v165.73,104.46 IO13.13 | v52.07,104.46 IO10.13 | v85.41,104.46 IO11.13 | v132.4,104.46 IO12.13 | C10.1 v60.01,112.71 60.01,110.49 | 110.49,62.87 C9.1 T5.2 | 71.44,66.68 BAT.- | 71.44,62.87 71.44,61.91 | 118.74,22.86 116.21,22.54 | 116.21,22.54 C4.1 v116.21,20 | SW4.3 SW3.1 | SW4.3 SW4.1 114.62,22.54 116.21,22.54 | SW3.1 SW3.3 | 51.12,44.77 60.3,37.43 | 60.3,37.43 60.64,37.15 | 113.98,197.17 arc-27 153.04,185.74 | v139.06,193.04 138.75,192.41 142.56,190.82 147,188.91 153.09,185.84 | v137.8,189.55 137.8,182.88 139.06,181.61 139.06,179.39 117.16,157.48 | SW4.3 SW3.1 | 60.64,37.15 89.53,20.95 | 60.64,37.15 60.64,37.14 60.3,37.43 | IO19.3 134.3,73.34
  Bottom 0.61: 140.33,110.49 137.8,110.49 127,110.49 126.37,111.12 101.92,111.12 100.65,109.86 94.93,109.86 94.3,110.49 93.35,110.49 | 90.49,110.49 93.35,110.49 | 57.15,110.49 60.01,110.49 61.28,110.49 61.91,109.86 67.63,109.86 68.26,110.49 74.93,110.49 | 140.33,110.49 C12.1 v140.33,112.71 | 137.48,110.49 IO12.8 | 170.82,110.49 173.67,110.49 C13.1 v173.67,112.71 | 170.82,110.49 IO13.8 | C11.1 v93.35,112.71 93.35,110.49 | 90.49,110.49 IO11.8 | 57.15,110.49 IO10.8 | 140.33,110.49 141.29,110.49 141.92,109.86 147.64,109.86 148.27,110.49 170.82,110.49 | 74.93,110.49 90.49,110.49 | ISP1.6 89.53,61.91 89.85,61.91 89.85,62.87 | 73.98,67.63 BAT.- 71.44,66.36 | 71.44,66.36 71.44,66.68 | 71.44,66.36 71.44,62.87 | T5.2 C9.1 109.86,63.18 109.47,62.8 IO9.3 105.09,62.8 105.09,62.23 | IO18.1 129.22,73.34 | 129.22,73.34 131.76,73.34 | 131.76,73.34 IO19.3 | 89.85,62.87 89.85,66.99 87.95,68.9 P1.1 84.14,67.95 84.14,64.14 82.87,62.87 71.44,62.87 | 73.98,67.63 73.98,64.77 | SW1.1 SW1.3 v101.92,36.2 SW2.1 SW2.3 88.9,36.2 71.44,53.66 71.44,62.87 | 73.98,67.63 76.83,67.63 | 63.18,66.36 IO15.4 | 63.18,66.36 61.91,66.36 58.74,69.85 58.74,73.66 56.2,76.2 45.72,76.2 37.78,84.14 37.78,105.41 42.86,110.49 57.15,110.49 | 106.68,65.41 106.68,67.63 113.67,74.61 117.16,74.61 118.43,73.34 IO18.1 | IO18.1 127.64,79.38 125.09,81.92 118.43,81.92 115.89,79.38 112.71,79.38 108.58,75.25 105.73,75.25 105.73,78.42 | 105.73,78.42 IO20.1 | 105.73,78.42 C19.- | 74.93,110.49 74.93,134.94 77.47,137.48 | 135.57,73.66 136.21,73.03 136.21,72.71 134.94,72.71 134.3,73.34 | 131.76,73.34 131.13,72.71 129.22,72.71 129.22,73.34 | 105.09,62 IO9.21 89.85,62 89.85,62.87
  Bottom 0.61: 105.09,62 105.09,62.23 | IO9.5 105.09,61.2 105.09,62 | 105.09,62.23 105.09,63.82 105.41,64.14 | 63.18,66.36 71.44,66.36
  Bottom 0.813: 83.82,155.89 C16.2 | 83.82,166.05 C17.2
  Bottom 1.422: 83.82,160.97 83.82,155.89 83.82,154.31 77.47,154.31 77.47,137.48 C15.C- C14.C- | 83.82,160.97 83.82,166.05 83.82,171.77 C18.C- | 83.82,160.97 IO14.2 100.01,160.97 103.51,157.48 117.16,157.48 M1.-
  pour Bottom (isolate 0.813): 0,0 219.71,0 219.71,219.71 0,219.71
GREEN  (via drill 0.3 pad 1.68, 0.6 pad 1.68)
  Top 0.61: v106.04,113.35 v106.04,103.51
  Top 0.813: v93.03,88.58 v93.03,84.77 | v69.22,84.77 v69.22,88.58 | v140.02,84.77 v140.02,88.9 | v159.07,84.14 v163.51,84.14
  Bottom 0.406: v93.03,84.77 93.03,84.46 | 140.02,84.14 v140.02,84.77 | 69.22,84.46 v69.22,84.77
  Bottom 0.61: v106.04,113.35 106.04,115.57 DT1.A2 | 93.03,89.85 94.93,89.85 106.04,100.97 DT2.A2 v106.04,103.51
  Bottom 0.813: 69.22,84.46 93.03,84.46 101.6,84.46 104.77,87.63 125.09,87.63 128.59,84.14 140.02,84.14 142.87,84.14 | DISP3.5 140.02,89.85 v140.02,88.9 | DISP2.5 93.03,89.85 v93.03,88.58 | DISP1.5 69.22,89.85 v69.22,88.58 | 142.87,84.14 v159.07,84.14 | T1.2 144.78,79.06 142.87,80.96 142.87,84.14 | DISP4.5 171.45,86.68 168.91,84.14 v163.51,84.14
  pour Bottom (isolate 0.813): 128.59,84.14 128.59,75.25 137.48,75.25 137.48,68.26 148.91,68.26 148.91,84.14
GREEN_LED  (via drill 0.8 pad 1.93)
  Top 0.61: v163.83,22.86 v148.27,49.21
  Bottom 0.61: D59.A2 D58.A2 D57.A2 D56.A2 D55.A2 D54.A2 D53.A2 38.1,181.61 D52.A2 D51.A2 D50.A2 D49.A2 D48.A2 D47.A2 D46.A2 D45.A2 D44.A2 D43.A2 D42.A2 D41.A2 D40.A2 D39.A2 D38.A2 38.1,38.42 D37.A2 D36.A2 D35.A2 D34.A2 D33.A2 D32.A2 D31.A2 D30.A2 D29.A2 D28.A2 D27.A2 D26.A2 D25.A2 v163.83,22.86 D24.A2 D23.A2 180.98,38.1 D22.A2 D21.A2 D20.A2 D19.A2 D18.A2 D17.A2 D16.A2 D15.A2 D14.A2 D13.A2 D12.A2 D11.A2 D10.A2 D9.A2 D8.A2 181.29,181.29 D7.A2 D6.A2 D5.A2 D4.A2 D3.A2 D2.A2 D1.A2 116.55,212.09 D60.A2 98.74,211.77
  Bottom 1.016: T3.2 142.56,48.26 142.87,49.85 145.41,51.12 147,50.8 v148.27,49.21
GREEN_T
  Bottom 0.406: IO9.13 102.55,57.22 102.55,53.02 109.54,46.04 R110.1
MISO  (via drill 0.6 pad 1.68)
  Top 0.406: v97.79,27.31 99.7,29.21 99.7,51.12 v97.79,53.02
  Bottom 0.406: ISP1.1 86.36,54.93 86.36,54.29 87.63,53.02 v97.79,53.02 100.01,55.25 100.01,57.25 IO9.16
  Bottom 0.61: R97.1 v97.79,27.31 SW3.2 SW3.4
  Bottom 0.813: 85.41,54.93 85.41,56.52 86.99,56.52 86.99,54.93 86.36,54.93 85.41,54.93
MOSI  (via drill 0.6 pad 1.68)
  Top 0.406: v113.03,33.66 v113.03,27.31
  Bottom 0.305: 84.77,57.47 87.63,57.47
  Bottom 0.406: 87.63,57.47 88.26,58.1 ISP1.4 | 84.77,57.47 84.14,56.83 84.14,53.98 86.99,51.12 100.65,51.12 | v113.03,27.31 SW4.2 | 100.97,57.21 IO9.15 100.87,54.61 100.65,54.29 100.65,51.12 | v113.03,33.66 114.3,33.66 115.25,34.61 115.25,37.47 114.3,38.42 105.09,38.42 100.65,42.86 100.65,51.12
  Bottom 0.61: SW4.2 SW4.4 106.04,26.67 105.41,27.31 R98.1
  Bottom 0.813: 88.26,59.06 89.85,59.06 89.85,58.1 88.26,58.1 88.26,59.06
N$1
  Bottom 0.406: D1.K 122.71,208.92 R1.2
N$2  (via drill 0.3 pad 1.68)
  Top 0.406: v143.51,192.09 v141.61,188.28
  Bottom 0.406: IO1.15 143.83,184.15 140.97,185.42 140.65,186.37 v141.61,188.28 | R1.1 122.24,205.08 122.24,204.15 143.51,196.53 144.78,194.63 v143.51,192.09
N$3
  Bottom 0.406: D2.K 133.19,207.01 R2.2
N$4
  Bottom 0.406: IO1.1 146.84,192.88 146.84,195.26 144.46,197.64 132.71,201.77 R2.1
N$5
  Bottom 0.61: DT1.K 111.12,120.02 112.08,120.97 114.93,120.97 115.89,120.02 115.89,114.94 R93.2
N$6
  Bottom 0.61: DT2.K R94.2
N$7  (via drill 0.3 pad 1.42)
  Top 0.406: v129.86,23.5 v129.22,26.99
  Bottom 0.406: IO4.15 125.41,29.53 128.59,30.16 v129.22,26.99 | v129.86,23.5 131.76,21.59 140.02,21.59 147,23.5 154.94,26.67 R25.1
N$8
  Bottom 0.406: D3.K 143.35,203.99 R3.2
N$9
  Bottom 0.406: D4.K 152.88,200.03 R4.2
N$10
  Bottom 0.406: D5.K 161.93,195.1 R5.2
N$11
  Bottom 0.406: D6.K 170.82,188.91 R6.2
N$12
  Bottom 0.406: IO11.14 84.14,105.09 83.19,104.14 57.79,104.14 57.15,104.78 IO10.9
N$13
  Bottom 0.406: IO12.14 131.13,105.09 130.17,104.14 124.78,104.14 120.97,107.95 103.19,107.95 99.38,104.14 91.12,104.14 90.49,104.78 IO11.9
N$14
  Bottom 0.406: IO1.2 148.11,192.72 148.11,196.06 145.41,198.75 R3.1
N$15
  Bottom 0.406: IO1.3 R4.1
N$16
  Bottom 0.406: IO1.4 150.34,191.45 152.88,193.99 155.42,193.99 R5.1
N$17
  Bottom 0.406: IO1.5 151.45,190.82 153.51,192.88 154.94,192.88 167.16,185.74 R6.1
N$18
  Bottom 0.406: IO1.6 152.56,190.18 153.99,191.61 155.1,191.61 175.1,179.86 R7.1
N$19
  Bottom 0.406: IO1.7 153.67,189.39 154.46,190.18 155.26,190.18 173.04,179.7 182.09,171.13 R8.1
N$20  (via drill 0.3 pad 1.42)
  Top 0.406: v189.87,137.8 v193.36,138.75
  Bottom 0.406: IO2.15 187.96,133.99 187.01,137.16 v189.87,137.8 | v193.36,138.75 195.26,139.38 196.21,140.34 190.82,160.02 R9.1
N$21
  Bottom 0.406: IO2.1 196.53,137.8 197.8,139.06 R10.1
N$22
  Bottom 0.61: IO10.1 48.26,119.7 47.62,120.33 R67.1
N$23
  Bottom 0.61: IO10.2 49.53,119.7 50.16,120.33 R66.1
N$24
  Bottom 0.61: IO10.4 52.07,119.06 55.25,122.24 R61.1
N$25
  Bottom 0.61: IO10.5 53.34,118.75 57.79,123.19 R62.1
N$26
  Bottom 0.406: IO10.15 49.53,105.41 49.21,105.09 46.99,105.09 R65.1
N$27
  Bottom 0.61: IO10.6 54.61,114.62 56.51,116.52 62.87,116.52 66.04,113.67 R63.1
N$28
  Bottom 0.61: IO10.7 55.88,114.3 56.83,115.25 61.28,115.25 62.87,113.67 R64.1
N$29
  Bottom 0.61: IO10.3 50.8,119.38 52.7,121.28 R68.1
N$30
  Bottom 0.61: IO11.3 84.14,119.38 86.04,121.28 R76.1
N$31
  Bottom 0.61: IO11.1 81.6,119.7 80.96,120.33 R75.1
N$32
  Bottom 0.61: IO11.2 82.87,119.7 83.5,120.33 R74.1
N$33
  Bottom 0.61: IO11.4 85.41,119.06 88.58,122.24 R69.1
N$34
  Bottom 0.61: IO11.5 86.68,118.75 91.12,123.19 R70.1
N$35
  Bottom 0.406: IO11.15 82.87,105.41 82.55,105.09 80.33,105.09 R73.1
N$36
  Bottom 0.61: IO11.6 87.95,114.62 89.85,116.52 96.52,116.52 99.38,113.67 R71.1
N$37
  Bottom 0.61: IO11.7 89.22,114.3 90.17,115.25 94.62,115.25 96.2,113.67 R72.1
N$38
  Bottom 0.406: D9.K 192.09,166.37 R9.2
N$39
  Bottom 0.406: D10.K 197.49,157.48 R10.2
N$40
  Bottom 0.406: D11.K 201.93,148.27 R11.2
N$41
  Bottom 0.406: D12.K 205.42,138.11 R12.2
N$42
  Bottom 0.406: D13.K 207.96,128.27 R13.2
N$43
  Bottom 0.406: D14.K 209.23,117.79 R14.2
N$44
  Bottom 0.406: IO12.9 137.48,104.78 138.11,104.14 163.51,104.14 164.47,105.09 IO13.14
N$45
  Bottom 0.406: D15.K 209.55,107 R15.2
N$46
  Bottom 0.406: D16.K 208.6,96.52 R16.2
N$47
  Bottom 0.61: DISP2.8 R76.2
N$48
  Bottom 0.61: IO12.3 131.13,119.38 133.03,121.28 R84.1
N$49
  Bottom 0.61: IO12.1 128.59,119.7 127.95,120.33 R83.1
N$50
  Bottom 0.61: IO12.2 129.86,119.7 130.49,120.33 R82.1
N$51
  Bottom 0.61: IO12.4 132.4,119.06 135.57,122.24 R77.1
N$52
  Bottom 0.61: IO12.5 133.67,118.75 138.11,123.19 R78.1
N$53
  Bottom 0.406: IO12.15 129.86,105.41 129.54,105.09 127.64,105.09 R81.1
N$54
  Bottom 0.61: IO12.6 134.94,114.62 136.84,116.52 143.51,116.52 146.37,113.67 R79.1
N$55
  Bottom 0.61: IO12.7 136.21,114.3 137.16,115.25 141.61,115.25 143.19,113.67 R80.1
N$56
  Bottom 0.61: R84.2 DISP3.8
N$57
  Bottom 0.61: IO13.3 164.47,119.38 166.37,121.28 R92.1
N$58
  Bottom 0.61: IO13.1 161.93,119.7 161.29,120.33 R91.1
N$59
  Bottom 0.61: IO13.2 163.19,119.7 163.83,120.33 R90.1
N$60
  Bottom 0.61: IO13.4 165.73,119.06 168.91,122.24 R85.1
N$61
  Bottom 0.61: IO13.5 167.01,118.75 171.45,123.19 R86.1
N$62
  Bottom 0.406: IO13.15 163.19,105.41 162.88,105.09 160.65,105.09 R89.1
N$63
  Bottom 0.61: R103.1 T5.1
N$64
  Bottom 0.406: IO9.7 108.05,59.6 109.22,58.42 111.44,58.42 113.03,60.01 R103.2
N$65
  Bottom 0.406: IO4.1 128.27,21.66 128.27,20.64 129.22,19.69 139.7,19.69 R26.1
N$67
  Bottom 0.406: D25.K 157.16,21.91 R25.2
N$68
  Bottom 0.406: D26.K 147.95,17.46 R26.2
N$69
  Bottom 0.406: D27.K 138.11,13.97 R27.2
N$70
  Bottom 0.406: D28.K 127.64,11.43 R28.2
N$71
  Bottom 0.406: D7.K 178.43,182.25 R7.2
N$72
  Bottom 0.406: IO9.22 98.51,62.87 96.84,62.87 96.2,63.5 96.2,66.04 P1.2
  Bottom 0.61: RFOTO.1 P1.3 87.95,73.98 P1.2
N$73
  Bottom 0.406: D29.K 117.16,10.16 R29.2
N$74
  Bottom 0.406: D30.K 106.68,9.84 R30.2
N$75
  Bottom 0.406: D31.K 96.2,10.8 R31.2
N$76
  Bottom 0.406: D32.K 86.36,12.7 R32.2
N$77
  Bottom 0.406: IO4.2 127,21.46 127,20.32 129.31,18.01 R27.1
N$78
  Bottom 0.406: IO4.3 125.73,21.27 125.73,16.83 R28.1
N$79
  Bottom 0.406: IO4.4 124.46,20 124.46,16.51 123.19,14.92 116.84,14.61 116.85,14.27 R29.1
N$80
  Bottom 0.406: IO4.5 123.19,20.88 123.19,17.15 121.92,15.88 107.95,15.88 106.84,14.76 R30.1
N$81
  Bottom 0.61: T2.3 158.43,75.25 R109.2
N$82
  Bottom 0.406: D8.K 185.9,174.47 R8.2
N$83
  Bottom 0.406: IO2.2 196.85,136.53 199.07,138.75 197.49,146.05 R11.1
N$84  (via drill 0.6 pad 1.42)
  Top 0.406: v103.51,71.12 99.38,66.99 v87.31,66.99
  Bottom 0.406: IO9.29 103.19,65.97 103.19,70.8 v103.51,71.12
  Bottom 0.61: v87.31,66.99 86.36,66.04 ISP1.5 R102.1
N$85
  Bottom 0.406: IO2.3 R12.1
N$86
  Bottom 0.406: IO2.4 200.02,134.62 201.93,133.67 203.2,127.32 R13.1
N$87
  Bottom 0.406: IO2.5 199.71,133.03 200.98,132.08 204.15,117.16 R14.1
N$88
  Bottom 0.406: IO2.6 199.07,131.76 200.02,131.13 204.79,107.95 R15.1
N$89
  Bottom 0.406: IO2.7 198.44,130.18 199.07,129.86 204.15,103.19 204.15,97.47 R16.1
N$90
  Bottom 0.406: IO1.9 150.18,180.02 arc-43 187.32,132.72 IO2.14
N$91  (via drill 0.3 pad 1.42)
  Top 0.406: v184.15,69.53 v187.64,67.31
  Bottom 0.406: IO3.15 180.02,68.26 181.61,70.8 v184.15,69.53 | v187.64,67.31 188.91,66.68 191.77,66.68 201.93,87 R17.1
N$92
  Bottom 0.406: IO3.1 188.6,64.45 192.09,64.45 198.76,77.79 R18.1
N$93
  Bottom 0.406: D17.K 206.69,86.36 R17.2
N$94
  Bottom 0.406: D18.K 203.83,76.2 R18.2
N$95
  Bottom 0.406: D19.K 199.71,66.68 R19.2
N$96
  Bottom 0.406: D20.K 194.94,57.79 R20.2
N$97
  Bottom 0.406: D21.K 188.6,48.9 R21.2
N$98
  Bottom 0.406: D22.K 182.24,40.96 R22.2
N$99
  Bottom 0.406: D23.K 174.31,33.66 R23.2
N$100
  Bottom 0.406: D24.K 166.37,27.62 R24.2
N$101
  Bottom 0.406: IO3.2 187.96,63.18 193.04,63.18 195.58,68.58 R19.1
N$102
  Bottom 0.406: IO3.3 R20.1
N$103
  Bottom 0.406: IO4.6 121.92,20.69 121.92,18.1 120.97,17.15 98.74,17.15 96.92,15.32 R31.1
N$104
  Bottom 0.406: IO3.4 186.69,60.96 188.52,59.13 arc-45 188.6,58.95 188.6,55.88 185.42,52.07 R21.1
N$105
  Bottom 0.406: IO3.5 185.74,60.01 187.32,58.42 187.32,55.88 178.75,45.72 178.75,44.77 R22.1
N$106
  Bottom 0.406: IO3.6 185.1,59.06 186.05,58.1 186.05,55.88 171.13,39.37 171.13,37.78 R23.1
N$107
  Bottom 0.406: IO3.7 184.47,57.79 184.79,57.47 184.79,56.3 163.51,33.02 163.51,31.75 R24.1
N$108
  Bottom 0.406: IO2.9 188.91,126.68 arc-43 178.75,67.63 IO3.14
N$109
  Bottom 0.406: IO4.7 120.65,20.49 120.65,19.05 120.01,18.42 88.58,18.42 87.26,17.09 R32.1
N$110
  Bottom 0.406: IO3.9 175.26,62.23 arc-44 124.14,30.16 IO4.14
N$111  (via drill 0.3 pad 1.42)
  Top 0.406: v61.59,39.69 v59.37,36.51
  Bottom 0.406: IO5.15 60.64,44.13 63.5,41.91 v61.59,39.69 | v59.37,36.51 57.79,34.61 57.79,33.66 R33.1
N$112
  Bottom 0.406: IO5.1 54.93,35.56 54.93,33.97 68.58,24.13 R34.1
N$113
  Bottom 0.406: D33.K 75.88,15.88 R33.2
N$114
  Bottom 0.406: D34.K 66.36,19.69 R34.2
N$115
  Bottom 0.406: D35.K 57.47,24.77 R35.2
N$116
  Bottom 0.406: D36.K 48.58,30.8 R36.2
N$117
  Bottom 0.406: D37.K 40.96,37.15 R37.2
N$118
  Bottom 0.406: D38.K 33.66,45.09 R38.2
N$119
  Bottom 0.406: R39.2 26.99,53.66 D39.K
N$120
  Bottom 0.406: D40.K 21.59,62.55 R40.2
N$121
  Bottom 0.406: IO5.2 53.02,35.24 53.02,33.66 59.69,28.89 R35.1
N$122
  Bottom 0.406: IO5.3 R36.1
N$123
  Bottom 0.406: IO5.4 50.8,36.83 47.94,36.83 R37.1
N$124
  Bottom 0.406: IO5.5 50.48,38.42 48.26,38.42 37.15,48.26 R38.1
N$125
  Bottom 0.406: IO5.6 50.16,40.01 48.58,40.01 41.27,46.36 30.8,56.2 R39.1
N$126
  Bottom 0.406: IO5.7 49.85,41.28 48.9,41.28 38.42,50.48 31.43,57.47 26.04,65.09 R40.1
N$127
  Bottom 0.406: IO4.9 117.79,29.21 arc-43 60.33,45.72 IO5.14
N$128  (via drill 0.3 pad 1.42)
  Top 0.406: v25.08,99.38 v21.59,99.38
  Bottom 0.406: IO6.15 27.94,102.55 27.94,99.38 v25.08,99.38 | v21.59,99.38 20.64,99.38 19.68,98.43 19.68,76.84 R41.1
N$129
  Bottom 0.406: IO6.1 18.73,101.28 18.1,100.65 18.1,82.97 R42.1
N$130
  Bottom 0.406: D41.K 17.15,71.44 R41.2
N$131
  Bottom 0.406: D42.K 13.65,81.28 R42.2
N$132
  Bottom 0.406: D43.K 11.43,91.44 R43.2
N$133
  Bottom 0.406: D44.K 9.84,102.23 R44.2
N$134
  Bottom 0.406: D45.K 9.52,112.4 R45.2
N$135
  Bottom 0.406: D46.K 10.79,123.19 R46.2
N$136
  Bottom 0.406: D47.K 12.7,133.35 R47.2
N$137
  Bottom 0.406: D48.K 15.56,143.51 R48.2
N$138
  Bottom 0.406: IO6.2 18.1,102.55 16.19,100.65 16.19,92.39 16.12,92.32 R43.1
N$139
  Bottom 0.406: IO6.3 15.57,103.82 arc45 15.39,103.75 R44.1
N$140
  Bottom 0.406: 13.97,112.29 arc45 13.9,112.47 R45.1 13.81,112.24 13.97,112.08 13.97,106.68 15.56,105.09 IO6.4
N$141
  Bottom 0.406: 15.01,122.68 R46.1 14.8,122.68 15.56,121.92 15.56,107.74 16.93,106.36 IO6.5
N$142
  Bottom 0.406: IO6.6 18.1,107.63 16.83,108.9 16.83,132.08 16.47,132.44 R47.1
N$143
  Bottom 0.406: R48.1 19.68,141.61 18.1,137.16 18.1,109.54 18.73,108.9 IO6.7
N$144
  Bottom 0.406: IO5.9 55.25,49.85 arc-44 28.89,103.82 IO6.14
N$145  (via drill 0.3 pad 1.42)
  Top 0.406: v45.4,165.42 v42.54,168.28
  Bottom 0.406: IO7.15 48.87,167.03 49.85,166.05 49.85,165.74 47.62,163.51 47.31,163.51 v45.4,165.42 | v42.54,168.28 41.91,168.91 39.69,168.91 25.4,154.62 23.81,151.13 R49.1
N$146
  Bottom 0.406: IO7.1 arc45 43.25,170.43 42.54,171.13 39.1,171.13 arc45 38.93,171.06 R50.1
N$147
  Bottom 0.406: D49.K 19.37,153.03 R49.2
N$148
  Bottom 0.406: D50.K 24.13,161.93 R50.2
N$149
  Bottom 0.406: D51.K 30.48,170.81 R51.2
N$150
  Bottom 0.406: D52.K 37.15,178.75 R52.2
N$151
  Bottom 0.406: D53.K 45.08,186.37 R53.2
N$152
  Bottom 0.406: D54.K 53.34,192.41 R54.2
N$153
  Bottom 0.406: D55.K 61.91,197.8 R55.2
N$154
  Bottom 0.406: D56.K 71.44,202.25 R56.2
N$155
  Bottom 0.406: IO7.2 44.16,171.31 arc45 44.09,171.49 41.91,173.67 39.31,173.67 arc45 39.13,173.6 R51.1
N$156
  Bottom 0.406: IO7.3 arc-45 44.96,172.21 40.96,176.21 40.61,176.21 arc45 40.43,176.14 R52.1
N$157
  Bottom 0.406: IO7.4 45.08,173.99 42.94,176.14 arc-45 42.86,176.32 42.86,178.12 48.26,182.88 R53.1 47.91,183.38 arc45 47.73,183.31
N$158
  Bottom 0.406: IO7.5 46.74,174.02 arc-45 46.57,174.1 44.45,176.21 44.45,177.7 arc-45 44.52,177.88 55.88,188.28 R54.1
N$159
  Bottom 0.406: R55.1 46.04,177.8 46.04,176.67 arc45 46.11,176.49 IO7.6
N$160
  Bottom 0.406: R56.1 47.62,177.8 47.62,176.53 47.76,176.53 arc-45 47.94,176.46 IO7.7
N$161
  Bottom 0.406: IO6.9 28.57,110.17 arc-44 51.12,166.05 IO7.14
N$162  (via drill 0.3 pad 1.68)
  Top 0.406: v102.87,198.75 v102.87,194.31
  Bottom 0.406: IO8.15 106.36,192.41 105.73,191.77 103.51,191.77 102.87,192.41 v102.87,194.31 | v102.87,198.75 102.87,199.71 100.65,201.93 83.5,201.93 83.44,201.86 R57.1
N$163
  Bottom 0.406: IO8.1 105.09,200.34 101.99,203.44 arc45 101.81,203.52 92.71,203.52 92.47,203.76 arc-45 92.39,203.94 R58.1
N$164
  Bottom 0.406: D57.K 81.28,205.74 R57.2
N$165
  Bottom 0.406: D58.K 91.44,208.28 R58.2
N$166
  Bottom 0.406: D59.K 101.92,209.55 R59.2
N$167
  Bottom 0.406: D60.K 112.71,209.87 R60.2
N$168
  Bottom 0.61: DISP1.7 R61.2
N$169
  Bottom 0.61: DISP1.6 R62.2
N$170
  Bottom 0.61: R63.2 66.04,98.11 65.09,97.16 60.64,97.16 55.25,91.76 DISP1.4
N$171
  Bottom 0.61: R64.2 60.33,99.38 52.7,91.76 DISP1.3
N$172
  Bottom 0.406: IO8.2 106.36,200.98 102.48,204.87 arc-45 102.4,205.04 R59.1
N$173
  Bottom 0.406: IO8.3 107.63,200.98 112.16,205.51 arc-45 112.34,205.58 R60.1
N$174
  Bottom 0.61: R65.2 50.16,94.3 DISP1.2
N$175
  Bottom 0.61: DISP1.9 R66.2
N$176
  Bottom 0.61: DISP1.10 R67.2
N$177
  Bottom 0.61: DISP1.8 R68.2
N$178
  Bottom 0.406: IO7.9 55.88,170.81 arc-40 107.63,190.82 IO8.14
N$179
  Bottom 0.61: IO13.6 168.27,114.62 170.18,116.52 177.8,116.52 179.39,114.94 R87.1
N$180
  Bottom 0.61: IO13.7 169.55,114.3 170.5,115.25 174.94,115.25 R88.1
N$181
  Bottom 0.61: R92.2 DISP4.8
N$182
  Bottom 0.61: DISP2.7 R69.2
N$183
  Bottom 0.61: R70.2 DISP2.6
N$184
  Bottom 0.61: DISP2.4 88.58,91.76 93.98,97.16 98.42,97.16 99.38,98.11 R71.2
N$185
  Bottom 0.61: DISP2.3 86.04,91.76 93.66,99.38 R72.2
N$186
  Bottom 0.61: R73.2 83.5,94.3 DISP2.2
N$187
  Bottom 0.61: DISP2.9 R74.2
N$188
  Bottom 0.61: DISP2.10 R75.2
N$189
  Bottom 0.61: R77.2 DISP3.7
N$190
  Bottom 0.61: R78.2 DISP3.6
N$191
  Bottom 0.61: DISP3.4 135.57,91.76 140.97,97.16 145.41,97.16 146.37,98.11 R79.2
N$192
  Bottom 0.61: DISP3.3 133.03,91.76 140.65,99.38 R80.2
N$193
  Bottom 0.61: R81.2 130.49,94.62 DISP3.2
N$194
  Bottom 0.61: R82.2 DISP3.9
N$195
  Bottom 0.61: R83.2 DISP3.10
N$196
  Bottom 0.61: R85.2 DISP4.7
N$197
  Bottom 0.61: R86.2 DISP4.6
N$198
  Bottom 0.61: DISP4.4 168.91,91.76 179.39,102.23 R87.2
N$199
  Bottom 0.61: DISP4.3 166.37,91.76 176.53,101.92 R88.2
N$200
  Bottom 0.61: R89.2 163.83,94.3 DISP4.2
N$201
  Bottom 0.61: R90.2 DISP4.9
N$202
  Bottom 0.61: R91.2 DISP4.10
N$204
  Bottom 0.813: IO14.1 C16.1
  Bottom 1.422: IO14.1 92.39,158.43 93.98,156.84 93.98,147.64 | 93.98,147.64 M1.+ | C15.C+ C14.C+ 93.98,143.83 93.98,147.64
N$205
  Bottom 0.406: IO9.10 104.77,57.21 104.77,56.2 106.36,54.61 115.25,54.61 120.97,60.33 138.43,60.33 140.33,58.42 153.99,58.42 156.21,60.64 156.21,65.41 157.48,66.68 R109.1
N$206
  Bottom 0.61: T1.3 150.49,81.6 152.08,80.01 R108.2
N$207
  Bottom 0.61: R111.2 129.22,42.23 T4.3
N$208
  Bottom 0.406: R108.1 153.04,66.68 154.3,65.41 154.3,60.96 153.04,59.69 141.92,59.69 140.02,61.6 120.65,61.6 114.93,55.88 106.68,55.88 105.67,56.89 IO9.9
N$209
  Bottom 0.61: R110.2 140.65,46.04 T3.3
N$210
  Bottom 0.406: R106.1 IO16.1
N$212
  Bottom 0.813: K2.2 IO16.4
  pour Bottom (isolate 0.254): 130.49,58.74 130.49,56.83 136.21,56.83 136.21,58.74
N$213
  Bottom 0.406: IO9.12 103.19,57.22 103.19,54.61 109.22,48.58 IO17.2
N$214
  Bottom 0.406: IO15.1 Q1.2
N$215
  Bottom 0.406: IO15.2 Q1.1
N$216
  Bottom 0.406: IO9.23 97.7,63.6 97.15,64.14 97.15,70.8 91.76,76.2 78.74,76.2 75.57,73.03 71.76,73.03 71.12,73.66 R100.1 71.12,75.56 70.48,76.2 66.36,76.2 63.82,73.66 63.82,71.75 64.45,71.12 IO15.6
N$217
  Bottom 0.406: IO9.24 98.48,64.4 98.11,64.77 98.11,71.75 92.39,77.47 73.98,77.47 | 73.98,77.47 65.72,77.47 62.55,74.3 62.55,71.44 63.18,70.8 IO15.5 | 73.98,77.47 R101.1
N$219
  Bottom 0.406: IO9.2 108.36,63.6 108.9,64.14 108.9,65.72 113.98,70.8 121.6,70.8 R104.1 121.92,70.8
  Bottom 0.61: 121.92,70.8 IO18.2 IO19.2
  pour Bottom (isolate 0.254): 130.18,71.75 136.21,71.75 136.21,69.85 130.18,69.85
N$221
  Bottom 0.813: K2.1 IO16.3
  pour Bottom (isolate 0.254): 130.49,55.56 136.21,55.56 136.21,53.66 130.49,53.66
N$223
  Bottom 0.406: IO9.11 104.14,57.23 104.14,55.25 106.04,53.34 115.89,53.34 117.48,54.93 IO16.2
N$224
  Bottom 0.406: R107.1 IO17.1
N$225
  Bottom 0.813: K3.2 IO17.4
  pour Bottom (isolate 0.254): 130.49,52.39 136.21,52.39 136.21,50.48 130.49,50.48
N$226
  Bottom 0.813: K3.1 IO17.3
  pour Bottom (isolate 0.254): 130.49,47.31 136.21,47.31 136.21,49.21 130.49,49.21
N$229  (via drill 0.8 pad 2.54, 0.81 pad 2.54)
  Bottom 0.61: v143.83,63.18 120.65,63.18 118.43,65.41 T5.3
  Bottom 0.813: v151.45,63.18 REP1.- v143.83,63.18
RED  (via drill 0.6 pad 1.68)
  Top 0.61: v111.12,103.51 v111.12,113.35
  Bottom 0.61: DT1.A1 113.67,116.84 111.12,114.62 v111.12,113.35 | 117.79,89.85 117.79,101.6 115.89,103.51 v111.12,103.51 DT2.A1
  Bottom 0.813: 80.96,86.68 48.9,86.68 47.62,87.95 DISP1.1 | 161.29,86.68 DISP4.1 | 80.96,86.68 DISP2.1 | 161.29,86.68 129.54,86.68 127.95,88.27 DISP3.1 117.79,89.85 103.51,89.85 100.33,86.68 80.96,86.68 | 161.29,86.68 161.29,80.33 160.02,79.06 T2.2
  pour Bottom (isolate 0.813): 180.98,86.68 161.29,86.68 161.29,84.14 157.16,84.14 157.16,65.41 170.5,65.41 180.98,75.88
RED_LED  (via drill 0.8 pad 1.93)
  Top 0.61: v135.26,15.88 v128.59,37.15
  Bottom 0.406: D1.A1 119.38,207.01
  Bottom 0.61: D59.A1 D58.A1 D57.A1 D56.A1 D55.A1 D54.A1 D53.A1 D52.A1 D51.A1 D50.A1 D49.A1 D48.A1 D47.A1 D46.A1 D45.A1 D44.A1 D43.A1 D42.A1 D41.A1 D40.A1 D39.A1 D38.A1 D37.A1 D36.A1 D35.A1 D34.A1 D33.A1 D32.A1 D31.A1 D30.A1 D29.A1 D28.A1 v135.26,15.88 D27.A1 D26.A1 D25.A1 D24.A1 D23.A1 D22.A1 D21.A1 D20.A1 D19.A1 D18.A1 D17.A1 D16.A1 D15.A1 D14.A1 D13.A1 D12.A1 D11.A1 D10.A1 D9.A1 D8.A1 D7.A1 D6.A1 D5.A1 D4.A1 D3.A1 D2.A1 D1.A1 D60.A1 99.38,206.69
  Bottom 1.016: v128.59,37.15 132.4,38.42 133.03,39.37 T4.2
RED_T
  Bottom 0.406: IO9.14 101.6,57.23 101.6,51.75 108.9,44.45 115.57,44.45 117.79,42.23 R111.1
S$1
  Bottom 0.813: 86.99,61.28 86.36,60.64 85.41,60.64 85.41,62.23 86.99,62.23 86.99,61.28
SCK
  Bottom 0.305: 89.85,60.01 87.63,60.01
  Bottom 0.406: 87.63,60.01 86.99,59.37 ISP1.3 | 89.85,60.01 90.49,60.01 92.08,58.42 93.98,58.42 R96.1 94.3,58.42 97.15,58.42 97.53,58.8 IO9.17
  Bottom 0.61: ISP1.3 83.82,58.74 82.55,57.47 82.55,48.9 SW2.4 SW2.2
  Bottom 0.813: 86.99,59.37 85.41,59.37 85.41,58.42 86.68,58.42 86.99,58.74 86.99,59.37
STROBE
  Bottom 0.406: IO13.12 167.01,103.51 166.37,102.87 133.67,102.87 | 86.68,102.87 100.01,102.87 103.82,106.68 120.33,106.68 124.14,102.87 133.67,102.87 | 86.68,102.87 53.34,102.87 | 53.34,102.87 IO10.12 | 86.68,102.87 IO11.12 | 133.67,102.87 IO12.12 | 53.34,102.87 44.13,102.87 41.27,100.01 41.27,87 48.26,80.01 93.98,80.01 100.01,73.98 100.01,67.63 100.87,66.77 IO9.26
STROBE_LED  (via drill 0.7 pad 1.78)
  Top 0.406: v121.92,113.35 v121.92,79.38
  Bottom 0.406: IO1.12 146.37,180.66 arc-47 187.01,129.86 | 187.01,129.86 IO2.12 | 176.53,66.04 IO3.12 | 176.53,66.04 arc48 187.01,129.86 | 121.29,30.8 arc48 176.53,66.04 | 121.29,30.8 IO4.12 | 58.74,47.94 arc48 121.29,30.8 | 29.53,106.36 arc48 58.74,47.94 | 53.98,167.32 arc48 29.53,106.36 | 53.98,167.32 arc-45 110.17,189.87 IO8.12 | IO7.12 53.66,167.64 53.98,167.32 | 29.53,106.36 IO6.12 | 58.74,47.94 IO5.12 | v121.92,79.38 121.92,78.42 120.33,76.84 113.03,76.84 104.87,68.68 IO9.31 | 122.87,154.31 122.87,155.57
  Bottom 0.61: 146.37,180.66 122.87,157.16 122.87,154.31 122.87,115.89 121.92,114.94 v121.92,113.35
TLAC1  (via drill 0.6 pad 1.68)
  Top 0.406: v113.03,57.79 v113.03,42.55
  Bottom 0.406: IO9.8 107.26,58.8 108.9,57.15 112.39,57.15 v113.03,57.79 | v113.03,42.55 SW1.2
  Bottom 0.61: R95.1 SW1.2 SW1.4

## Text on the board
Bottom: +5V | Gnd | PaJa | 2011 | Hodiny | AC 7-12V | rev. 31.03.11 | DS18B20 | +3V
tPlace: mustek nalezato
Doplnky: 60 | 5 | 10 | 45 | 15 | 30
hodiny: 12 | 9 | 3 | 6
